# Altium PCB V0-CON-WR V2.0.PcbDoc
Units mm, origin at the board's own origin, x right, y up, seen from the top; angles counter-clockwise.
Board outline 20.54 x 21.82 mm, 2 copper layers (Top Layer, Bottom Layer), stack 0.871 mm thick; 7 components, 6 nets, 46 pads, 49 vias.
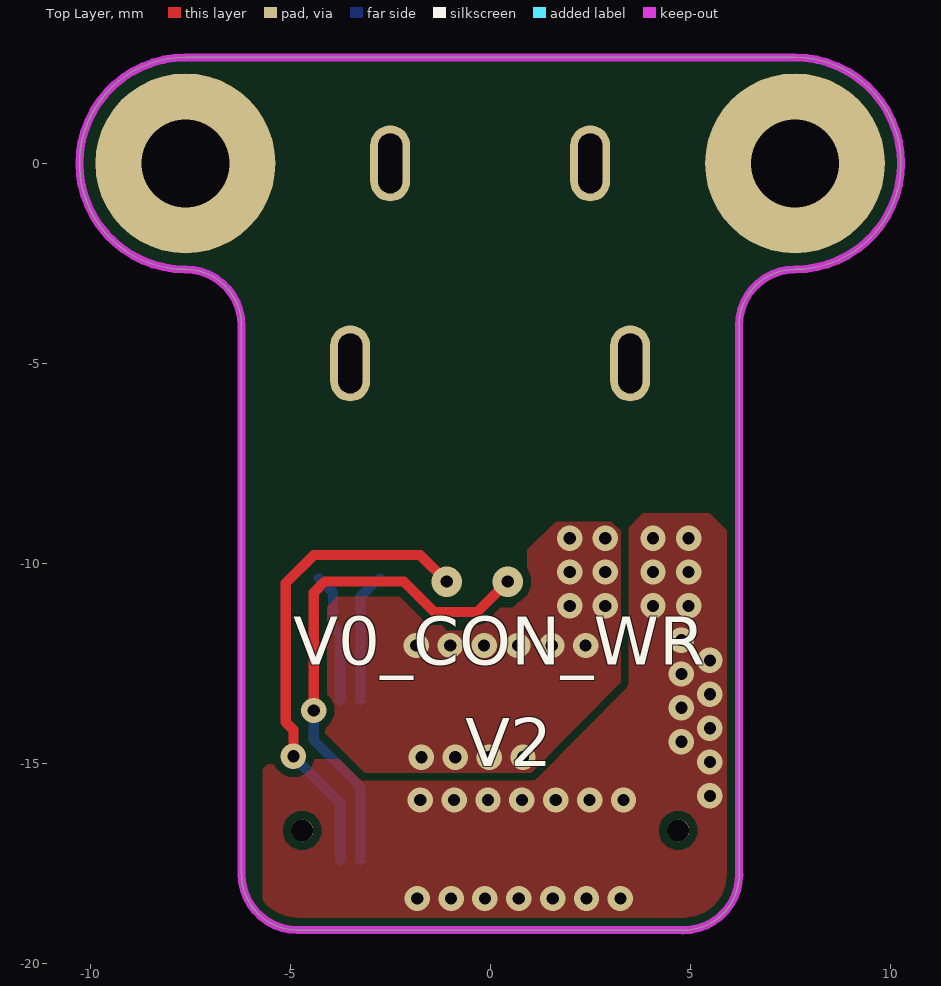
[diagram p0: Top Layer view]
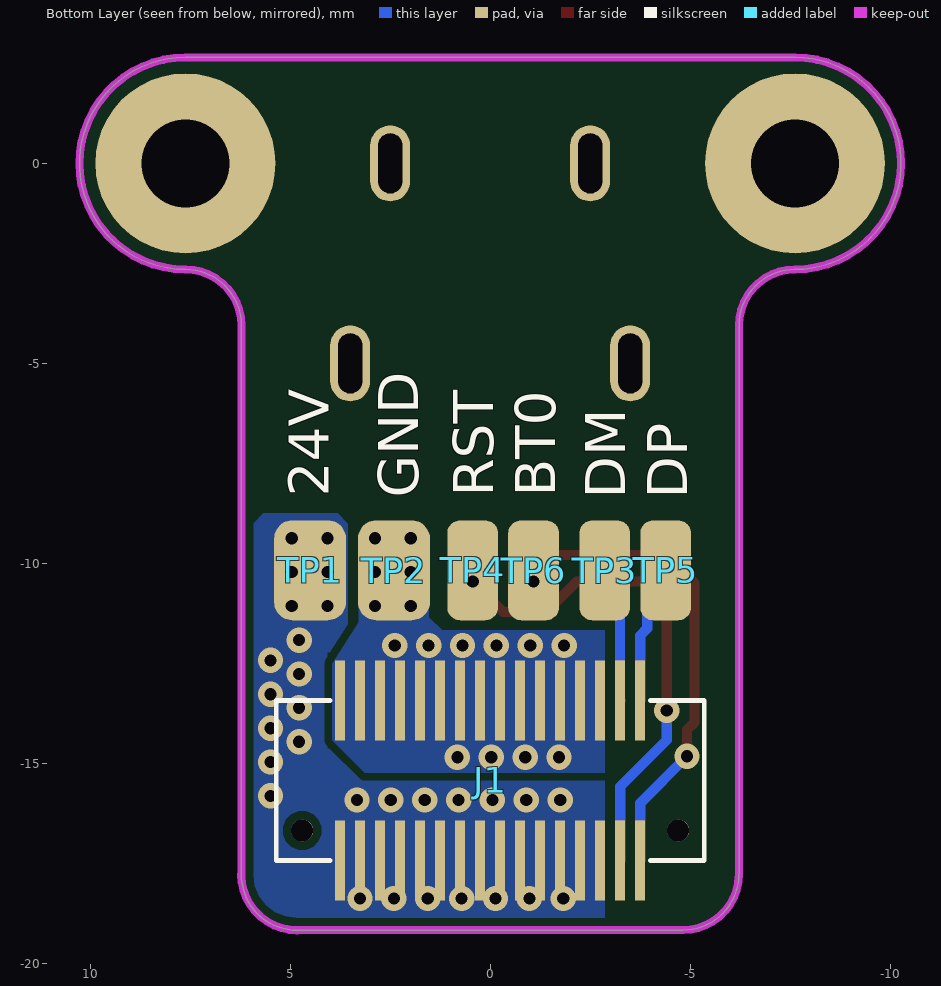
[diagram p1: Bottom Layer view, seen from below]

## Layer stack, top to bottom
Top Solder: solder mask 0.0102, Solder Resist, Dk 3.5
Top Layer: signal copper 0.0356
Dielectric 1: dielectric 0.8, FR-4, Dk 4.8
Bottom Layer: signal copper 0.0356
Bottom Solder: solder mask 0.0102, Solder Resist, Dk 3.5

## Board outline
-6.22,-17.764 -6.22,-4.05 ccw(c-7.62,-4.05) -7.62,-2.65 cw(c-7.62,0) -7.62,2.65 7.62,2.65 cw(c7.62,0) 7.62,-2.65 ccw(c7.62,-4.05) 6.22,-4.05 6.22,-17.778 6.226,-17.772 cw(c4.826,-17.772) 4.826,-19.172 4.833,-19.165 -4.819,-19.165 -4.816,-19.168 cw(c-4.816,-17.768)

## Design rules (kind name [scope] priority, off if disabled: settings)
Clearance [All] p1: gap=0.203 ignorepadtopadclearanceinfootprint=FALSE
PolygonConnect [All] p1: connectstyle=Direct reliefconductorwidth=0.254 reliefentries=4 polygonreliefangle="90 Angle" airgapwidth=0.254
RoutingVias [All] p1: holewidth=0.711 width=1.27 viastyle="Through Hole" minholewidth=0.711 minwidth=1.27 maxholewidth=0.711 maxwidth=1.27
SolderMaskExpansion [All] p1: expansion=0.102 istentingtop=FALSE
Width [All] p1: maxlimit=0.254 minlimit=0.152 preferedwidth=0.203
30 further rules are at their usual default settings.

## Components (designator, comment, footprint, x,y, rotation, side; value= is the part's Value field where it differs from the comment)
J1 "Header 16X2A" BTB_2x16_0.5mm 5.35,-17.424 r180 bottom
TP1 "Testpoint 1.6mm" "Testpoint 1.6mm"#1 4.503,-10.173 r180 top
TP2 "Testpoint 1.6mm" "Testpoint 1.6mm"#1 2.407,-10.173 r0 top
TP3 "Testpoint 1.6mm" "Testpoint 1.6mm"#2 -2.863,-10.173 r0 top
TP4 "Testpoint 1.6mm" "Testpoint 1.6mm"#2 0.439,-10.173 r0 top
TP5 "Testpoint 1.6mm" "Testpoint 1.6mm"#2 -4.387,-10.173 r0 top
TP6 "Testpoint 1.6mm" "Testpoint 1.6mm"#2 -1.085,-10.173 r0 top

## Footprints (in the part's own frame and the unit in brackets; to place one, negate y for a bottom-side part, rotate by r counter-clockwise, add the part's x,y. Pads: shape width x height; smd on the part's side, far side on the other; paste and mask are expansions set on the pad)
BTB_2x16_0.5mm [mm]
  round 0.55 hole 0.55 unplated mask+0.102: 0(0.65,0.75) 0(10.05,0.75)
  rect 0.25x2 smd mask+0.05: 1(1.6,0) 2(2.1,0) 3(2.6,0) 4(3.1,0) 5(3.6,0) 6(4.1,0) 7(4.6,0) 8(5.1,0) 9(5.6,0) 10(6.1,0) 11(6.6,0) 12(7.1,0) 13(7.6,0) 14(8.1,0) 15(8.6,0) 16(9.1,0) 17(9.1,4) 18(8.6,4) 19(8.1,4) 20(7.6,4) 21(7.1,4) 22(6.6,4) 23(6.1,4) 24(5.6,4) 25(5.1,4) 26(4.6,4) 27(4.1,4) 28(3.6,4) 29(3.1,4) 30(2.6,4) 31(2.1,4) 32(1.6,4)
  silkscreen extent 0,0 10.7,4
"Testpoint 1.6mm"#1 [mm]
  rrect50% 1.8x2.5 smd far side paste-2 mask+0: 1(0,0)
"Testpoint 1.6mm"#2 [mm]
  rrect50% 1.27x2.5 smd far side paste-2 mask+0: 1(0,0)

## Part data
J1: "Header, 16-Pin, Dual row"

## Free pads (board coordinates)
  round 4.5 hole 2.2: 2(-7.62,0) 2(7.62,0)
  oval 1x1.9 hole 0.6 slot 1.5 at 90 deg: 3(-2.5,0) 4(2.5,0) 5(-3.5,-5) 6(3.5,-5)

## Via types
v1: diameter 0.635, hole 0.305, Top Layer to Bottom Layer, tented both sides, 47 vias
v2: diameter 0.762, hole 0.305, Top Layer to Bottom Layer, tented both sides, 2 vias

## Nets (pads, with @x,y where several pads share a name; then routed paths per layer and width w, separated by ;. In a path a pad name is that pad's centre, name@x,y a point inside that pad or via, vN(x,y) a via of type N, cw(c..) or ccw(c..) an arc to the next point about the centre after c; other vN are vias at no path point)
+24V: J1.1 J1.2 J1.3 J1.4 J1.5 J1.6 J1.7 J1.8 J1.9 J1.10 J1.11 J1.12 J1.13 J1.14 TP1.1
  other v1: -1.825,-18.377 -0.978,-18.377 -0.132,-18.377 0.715,-18.377 1.562,-18.377 2.408,-18.377 3.255,-18.377 -1.749,-15.914 -0.902,-15.914 -0.055,-15.914 0.791,-15.914 1.638,-15.914 2.485,-15.914 3.331,-15.914 5.493,-15.812 5.493,-14.965 4.779,-14.457 5.493,-14.119 4.779,-13.611 5.493,-13.272 4.779,-12.764 5.493,-12.425 4.779,-11.917 4.071,-11.062 4.96,-11.062 4.071,-10.216 4.96,-10.216 4.071,-9.369 4.96,-9.369
BOOT0: J1.16 TP6.1 | length 12.1
  Top Layer w0.254: v1(-4.921,-14.821) -4.921,-14.158 -5.111,-13.968 -5.111,-10.491 -4.413,-9.792 -1.746,-9.792 v2(-1.085,-10.453) ; v2@-0.997,-10.364 v2@-0.984,-10.376
  Bottom Layer w0.254: v1(-4.921,-14.821) -3.75,-15.992 J1.16
GND: J1.19 J1.20 J1.21 J1.22 J1.23 J1.24 J1.25 J1.26 J1.27 J1.28 J1.29 J1.30 J1.31 J1.32 TP2.1
  other v1: -1.72,-14.847 -0.874,-14.847 -0.027,-14.847 0.82,-14.847 -1.847,-12.053 -1.001,-12.053 -0.154,-12.053 0.693,-12.053 1.539,-12.053 2.386,-12.053 1.988,-11.062 2.877,-11.062 1.988,-10.216 2.877,-10.216 1.988,-9.369 2.877,-9.369
RESET: J1.15 TP4.1 | length 12.9
  Top Layer w0.254: v1(-4.413,-13.678) -4.413,-10.732 -4.133,-10.453 -2.163,-10.453 -1.401,-11.215 -0.323,-11.215 v2(0.439,-10.453) ; v2@0.439,-10.376 v2@0.54,-10.376
  Bottom Layer w0.254: v1(-4.413,-13.678) -4.413,-14.413 -3.25,-15.576 J1.15
RX/DM: J1.18 TP3.1 | length 3.3
  Bottom Layer w0.254: J1.18 -3.248,-13.422 -3.248,-10.837 TP3.1@-2.863,-10.453 ; TP3.1@-2.851,-10.465 TP3.1@-2.762,-10.376
TX/DP: J1.17 TP5.1 | length 3.3
  Bottom Layer w0.254: TP5.1@-4.286,-10.376 -3.927,-10.735 -3.927,-11.624 -3.75,-11.801 J1.17
pads on no net: J1.0

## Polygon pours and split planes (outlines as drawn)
+24V on Bottom Layer "NONET_L03_P-001" (solid, pour order 7): 3.817,-8.751 3.563,-9.003 3.563,-13.015 1.426,-15.152 -2.863,-15.152 -2.863,-19.089 6.23,-19.089 6.23,-9.31 5.671,-8.751
GND on Bottom Layer "NONET_L03_P-001" (solid, pour order 5): 1.201,-11.672 1.531,-11.342 1.531,-9.64 3.283,-9.64 3.283,-11.469 3.944,-12.51 3.944,-14.415 3.131,-15.228 -2.863,-15.228 -2.863,-11.672
GND on Top Layer "NONET_L03_P-001" (solid, pour order 4): -0.628,-11.679 -0.062,-11.113 0.566,-11.113 0.925,-10.757 0.925,-9.661 1.632,-8.954 3.029,-8.954 3.258,-9.183 3.258,-12.97 1.023,-15.228 -3.143,-15.228 -4.133,-14.237 -4.133,-11.138 -3.829,-10.834 -1.93,-10.834 -1.085,-11.679
+24V on Top Layer "NONET_L03_P-001" (solid, pour order 6): 3.458,-9.108 3.815,-8.751 5.493,-8.751 6.23,-9.487 6.23,-19.089 -5.686,-19.089 -5.686,-15.152 -5.432,-14.898 -3.425,-14.898 -3.171,-15.152 0.982,-15.152 3.458,-12.675

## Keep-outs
Keep-Out Layer:
  lines w0.2: -7.62,2.65 1.083,2.65 7.62,2.65 ; -6.22,-17.764 -6.22,-4.05 ; -4.819,-19.165 4.833,-19.165 ; 6.22,-17.778 6.22,-4.05
  lines w0.203: -7.62,2.65 ccw(c-7.62,0) -7.62,-2.65 cw(c-7.62,-4.05) -6.22,-4.05 ; -6.216,-17.768 ccw(c-4.816,-17.768) -4.816,-19.168 ; 4.826,-19.172 ccw(c4.826,-17.772) 6.226,-17.772 ; 6.22,-4.05 cw(c7.62,-4.05) 7.62,-2.65 ccw(c7.62,0) 7.62,2.65

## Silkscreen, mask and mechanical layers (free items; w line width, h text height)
Top Overlay:
  text "V0_CON_WR" at -4.921,-12.539 h1.2
  text "V2" at -0.628,-15.075 h1.2
Bottom Overlay:
  text "BT0" at -1.626,-8.331 h1 r270
  text "RST" at -0.076,-8.331 h1 r270
  text "24V" at 4.039,-8.331 h1 r270
  text "GND" at 1.803,-8.357 h1 r270
  text "DP" at -4.928,-8.382 h1 r270
  text "DM" at -3.378,-8.382 h1 r270
Mechanical 15:
  lines w0.254: -7.62,0 0,0 7.62,0 ; -0.25,-13.424 0.25,-13.424 ; 0,-13.424 0,6.565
